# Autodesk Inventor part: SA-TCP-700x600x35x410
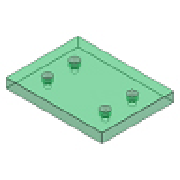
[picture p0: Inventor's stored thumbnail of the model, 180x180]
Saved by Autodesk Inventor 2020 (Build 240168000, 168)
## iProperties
Created: 2019-01
Part Number: SA-TCP-700x600x35x410
Material: S 55 C
Description: Top Clamping Plate
Document SubType Name: Modeling
Designer: LENOVO-CADCIM
Standard Revision: 1
Manufacturer: FUTABA
Language: en-US
Size Designation: 700x600x35x410
Categories: <MemberInstance><Categories><Category DisplayName="Mold" InternalName="349578f2-f4d4-4954-8c09-8e99297a61c0" Mnemonic="MOLD"><Category DisplayName="Mold Plates"
Density: 7.85 g/cm^3
Appearance: Clear - Green 1
IsCustomPart: 1
Author: LENOVO-CADCIM
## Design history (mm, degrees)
sketch "Sketch1"
  geometry: L1 (-300, 350)-(300, 350); L2 (300, 350)-(300, -350); L3 (300, -350)-(-300, -350); L4 (-300, -350)-(-300, 350); 3 further points
  constraints: 8 end point, 2 midpoint, 2 parallel, 1 horizontal, 1 horizontal alignment, 1 perpendicular, 1 vertical alignment
  dimensions: "d72" = 600 distance between parallel lines of L2 L4 (= W_); "d73" = 700 distance between parallel lines of L3 L1 (= L)
extrude "Extrusion1" new body sketch "Sketch1" distance "d20" = 35 (= H_); taper "d30" = 0 deg
feature "Sculpt1"
body "Solid1"
sketch "Sketch2"
  geometry: 2 further points
  dimensions: "d53" = 205 horizontal distance of point (0, 0) point (-205, 243) (= 0.5 x S1_W); "d54" = 243 vertical distance of point (0, 0) point (-205, 243) (= 0.5 x S1_L)
hole "Hole1" sketch "Sketch2" diameter "d55" = 18 (= S1_d1); stored, may be unused: countersink angle "d59" = 90 deg, drill point angle "d61" = 0 deg; dims "d56" = 6, "d57" = 26 (= S1_d2), "d58" = 17.5 (= S1_k), "d60" = 35 (= H_)
pattern_linear "Rectangular Pattern1" dims "d64" = 243 (computed from S1_L, Ns), "d67" = 410 (computed from S1_W, Nw)
chamfer "Chamfer1" distance "d68" = 0.5; stored, may be unused: second distance "d69" = 2, angle "d71" = 45 deg
feature "Surface1"
body "Srf1"
other parameters: "L" = 700 [user parameter; used in 1 equation term], "W_" = 600 [user parameter; used in 1 equation term], "H_" = 35 [user parameter; used in 2 equation terms], "S1_d1" = 18 [user parameter; used in 1 equation term], "S1_d2" = 26 [user parameter; used in 1 equation term], "S1_k" = 17.5 [user parameter; used in 1 equation term], "S1_L" = 486 [user parameter; used in 2 equation terms]
